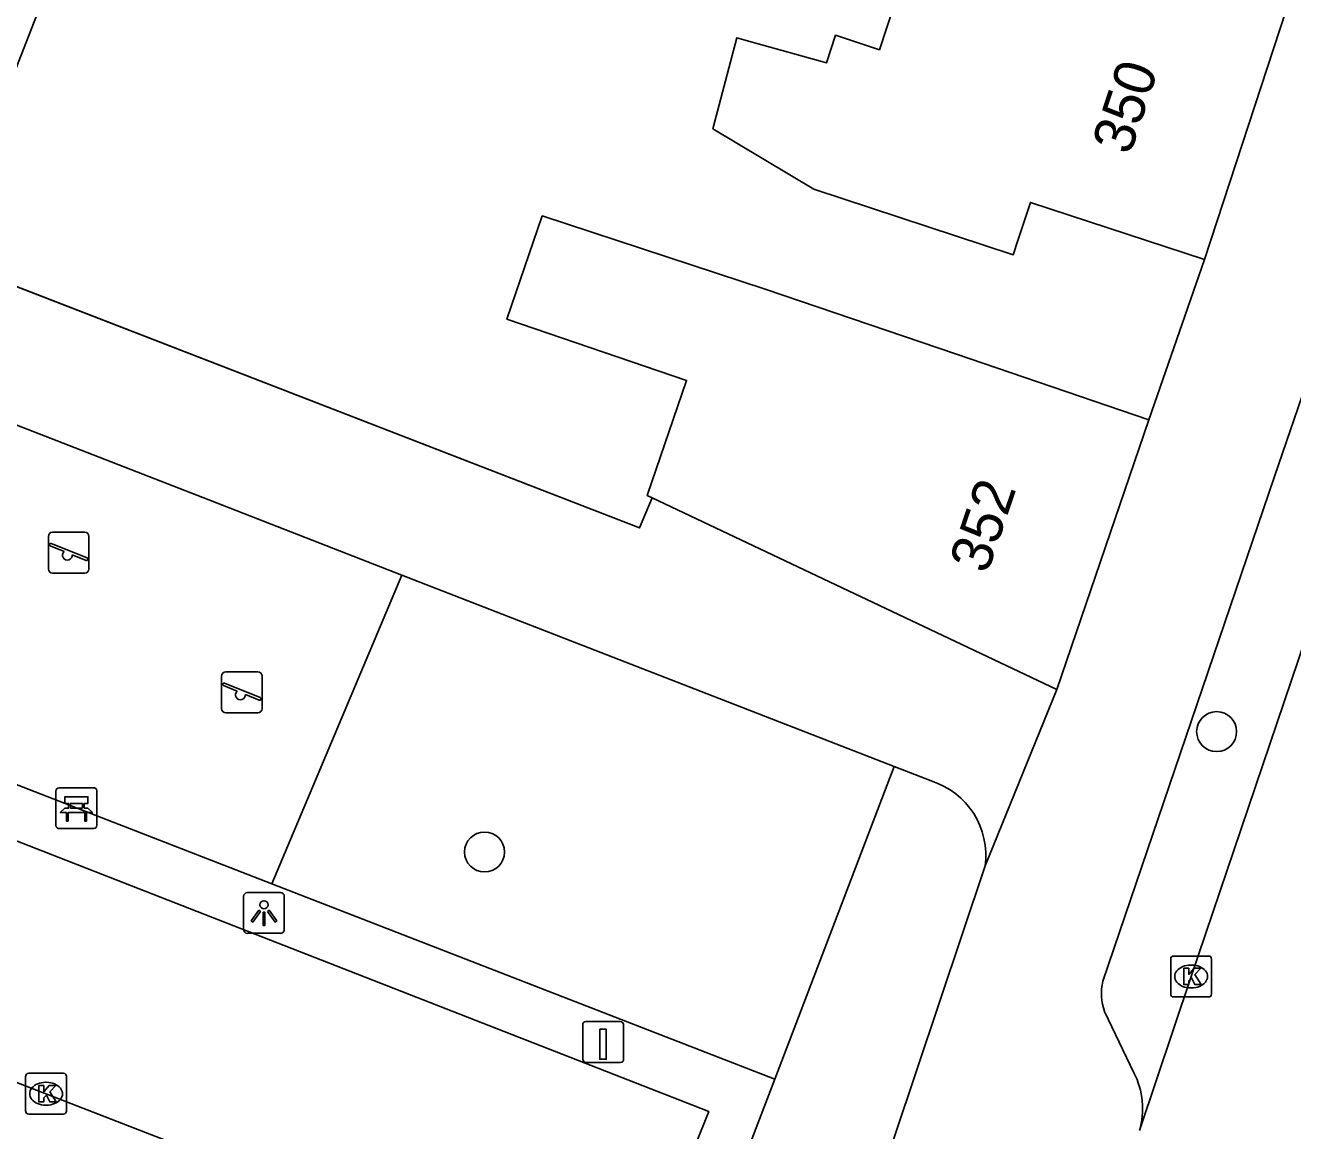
# Model space of a CAD drawing. Extents: x 161253 to 161848, y 384872 to 385383.
# Drawn here: x 161649.49 to 161680.51, y 385117.52 to 385144.57 of the extents above; entities that cross this region are included whole.
import ezdxf

# ---------------------------------------------------------------- set-up
doc = ezdxf.new("R2010")
doc.units = 0
for name, color, linetype in [('IMGEO_Bank', 7, 'Continuous'), ('IMGEO_Boom', 7, 'Continuous'), ('IMGEO_Groenvoorziening', 7, 'Continuous'), ('IMGEO_Hek', 7, 'Continuous'), ('IMGEO_Kolk', 7, 'Continuous'), ('IMGEO_Laadpaal', 7, 'Continuous'), ('IMGEO_Lichtpunt', 7, 'Continuous'), ('IMGEO_Muur', 7, 'Continuous'), ('IMGEO_Pand', 7, 'Continuous'), ('IMGEO_Pand_nummerreeks', 7, 'Continuous'), ('IMGEO_Rijbaan_lokaal_open', 7, 'Continuous'), ('IMGEO_Speelvoorziening', 7, 'Continuous'), ('IMGEO_Voetpad_open', 7, 'Continuous')]:
    doc.layers.add(name, color=color, linetype=linetype)

msp = doc.modelspace()

# ---------------------------------------------------------------- linework, layer by layer
at = {"layer": 'IMGEO_Bank'}
for p, q in [((161650.243, 385124.985), (161650.243, 385125.826)), ((161650.243, 385125.826), (161650.243, 385124.985)), ((161650.318, 385125.91), (161651.159, 385125.91)), ((161651.159, 385125.91), (161650.318, 385125.91)), ((161651.243, 385125.835), (161651.243, 385124.994)), ((161651.243, 385124.994), (161651.243, 385125.835)), ((161650.552, 385125.416), (161650.552, 385125.522)), ((161650.596, 385125.522), (161650.596, 385125.416)), ((161650.884, 385125.528), (161650.602, 385125.528)), ((161650.602, 385125.41), (161650.884, 385125.41)), ((161650.89, 385125.416), (161650.89, 385125.522)), ((161650.934, 385125.522), (161650.934, 385125.416)), ((161650.94, 385125.308), (161650.547, 385125.308)), ((161651.168, 385124.91), (161650.327, 385124.91)), ((161650.327, 385124.91), (161651.168, 385124.91))]:
    msp.add_line(p, q, dxfattribs=at)
for points in [[(161650.546, 385125.528), (161650.46, 385125.528), (161650.46, 385125.689), (161651.023, 385125.689), (161651.023, 385125.528), (161650.94, 385125.528)], [(161650.49, 385125.308), (161650.348, 385125.308), (161650.46, 385125.41), (161650.546, 385125.41)], [(161650.94, 385125.41), (161651.023, 385125.41), (161651.135, 385125.308), (161650.996, 385125.308)], [(161650.54, 385125.301), (161650.54, 385125.094), (161650.497, 385125.094), (161650.497, 385125.301)], [(161650.99, 385125.301), (161650.99, 385125.094), (161650.946, 385125.094), (161650.946, 385125.301)]]:
    msp.add_lwpolyline(points, dxfattribs=at)
for centre, radius, start, end in [((161650.321, 385125.832), 0.0779, 92.4484, 184.2845), ((161650.321, 385125.832), 0.0779, 92.4484, 184.2845), ((161651.165, 385125.832), 0.0779, 2.4484, 94.2845), ((161651.165, 385125.832), 0.0779, 2.4484, 94.2845), ((161650.545, 385125.521), 0.00671, 2.8957, 87.1043), ((161650.545, 385125.417), 0.00671, 272.8957, 357.1043), ((161650.602, 385125.521), 0.00671, 92.8957, 177.1043), ((161650.602, 385125.417), 0.00671, 182.8957, 267.1043), ((161650.884, 385125.521), 0.00671, 2.8957, 87.1043), ((161650.884, 385125.417), 0.00671, 272.8957, 357.1043), ((161650.941, 385125.521), 0.00671, 92.8957, 177.1043), ((161650.941, 385125.417), 0.00671, 182.8957, 267.1043), ((161650.49, 385125.301), 0.00671, 2.8957, 87.1043), ((161650.547, 385125.301), 0.00671, 92.8957, 177.1043), ((161650.939, 385125.301), 0.00671, 2.8957, 87.1043), ((161650.996, 385125.301), 0.00671, 92.8957, 177.1043), ((161650.321, 385124.988), 0.0779, 182.4484, 274.2845), ((161650.321, 385124.988), 0.0779, 182.4484, 274.2845), ((161651.165, 385124.988), 0.0779, 272.4484, 4.2845), ((161651.165, 385124.988), 0.0779, 272.4484, 4.2845)]:
    msp.add_arc(centre, radius, start, end, dxfattribs=at)
at = {"layer": 'IMGEO_Boom'}
for centre in [(161678.649, 385127.284), (161660.732, 385124.337)]:
    msp.add_circle(centre, 0.489, dxfattribs=at)
at = {"layer": 'IMGEO_Groenvoorziening'}
for points in [[(161658.707, 385131.117), (161655.526, 385123.562)], [(161670.754, 385126.431), (161667.834, 385118.779)]]:
    msp.add_lwpolyline(points, dxfattribs=at)
at = {"layer": 'IMGEO_Hek'}
for points in [[(161658.707, 385131.117), (161653.985, 385132.956)], [(161655.526, 385123.562), (161658.707, 385131.117)], [(161638.478, 385130.187), (161655.526, 385123.562)]]:
    msp.add_lwpolyline(points, dxfattribs=at)
at = {"layer": 'IMGEO_Kolk'}
for p, q in [((161677.524, 385120.864), (161677.524, 385121.716)), ((161677.599, 385121.79), (161678.451, 385121.79)), ((161678.525, 385121.716), (161678.525, 385120.864)), ((161678.012, 385121.57), (161678.037, 385121.57)), ((161678.035, 385121.01), (161678.01, 385121.01)), ((161678.451, 385120.79), (161677.599, 385120.79)), ((161649.501, 385117.994), (161649.501, 385118.846)), ((161649.576, 385118.92), (161650.428, 385118.92)), ((161650.502, 385118.846), (161650.502, 385117.994)), ((161649.989, 385118.7), (161650.014, 385118.7)), ((161650.428, 385117.92), (161649.576, 385117.92)), ((161650.012, 385118.14), (161649.987, 385118.14))]:
    msp.add_line(p, q, dxfattribs=at)
for points in [[(161677.524, 385120.864), (161677.524, 385121.716)], [(161677.599, 385121.79), (161678.451, 385121.79)], [(161678.525, 385121.716), (161678.525, 385120.864)], [(161677.845, 385121.49), (161677.968, 385121.49), (161677.968, 385121.339), (161678.098, 385121.49), (161678.262, 385121.49), (161678.116, 385121.339), (161678.269, 385121.09), (161678.117, 385121.09), (161678.032, 385121.254), (161677.968, 385121.187), (161677.968, 385121.09), (161677.845, 385121.09), (161677.845, 385121.49)], [(161678.451, 385120.79), (161677.599, 385120.79)], [(161649.501, 385117.994), (161649.501, 385118.846)], [(161649.576, 385118.92), (161650.428, 385118.92)], [(161650.502, 385118.846), (161650.502, 385117.994)], [(161649.822, 385118.62), (161649.945, 385118.62), (161649.945, 385118.469), (161650.075, 385118.62), (161650.239, 385118.62), (161650.093, 385118.469), (161650.246, 385118.22), (161650.094, 385118.22), (161650.009, 385118.384), (161649.945, 385118.317), (161649.945, 385118.22), (161649.822, 385118.22), (161649.822, 385118.62)], [(161650.428, 385117.92), (161649.576, 385117.92)]]:
    msp.add_lwpolyline(points, dxfattribs=at)
for centre, start, end in [((161677.601, 385121.714), 91.552, 178.448), ((161677.601, 385121.714), 91.552, 178.448), ((161678.449, 385121.714), 1.552, 88.448), ((161678.449, 385121.714), 1.552, 88.448), ((161677.601, 385120.866), 181.552, 268.448), ((161677.601, 385120.866), 181.552, 268.448), ((161678.449, 385120.866), 271.552, 358.448), ((161678.449, 385120.866), 271.552, 358.448), ((161649.578, 385118.844), 91.552, 178.448), ((161649.578, 385118.844), 91.552, 178.448), ((161650.426, 385118.844), 1.552, 88.448), ((161650.426, 385118.844), 1.552, 88.448), ((161649.578, 385117.996), 181.552, 268.448), ((161649.578, 385117.996), 181.552, 268.448), ((161650.426, 385117.996), 271.552, 358.448), ((161650.426, 385117.996), 271.552, 358.448)]:
    msp.add_arc(centre, 0.0765, start, end, dxfattribs=at)
for centre, major_axis, ratio, start_param, end_param in [((161678.011, 385121.29), (-0.387, 0.002), 0.722429, 4.712389, 7.853982), ((161678.036, 385121.29), (-0.39, 0.002), 0.717154, 1.570796, 4.712389), ((161649.988, 385118.42), (-0.387, 0.002), 0.722429, 4.712389, 7.853982), ((161650.013, 385118.42), (-0.39, 0.002), 0.717154, 1.570796, 4.712389)]:
    msp.add_ellipse(centre, major_axis=major_axis, ratio=ratio, start_param=start_param, end_param=end_param, dxfattribs=at)
at = {"layer": 'IMGEO_Laadpaal'}
for p, q in [((161663.135, 385120.102), (161663.135, 385119.261)), ((161663.135, 385120.102), (161663.135, 385119.261)), ((161664.051, 385120.186), (161663.21, 385120.186)), ((161664.051, 385120.186), (161663.21, 385120.186)), ((161664.135, 385119.27), (161664.135, 385120.111)), ((161664.135, 385119.27), (161664.135, 385120.111)), ((161663.219, 385119.186), (161664.06, 385119.186)), ((161663.219, 385119.186), (161664.06, 385119.186))]:
    msp.add_line(p, q, dxfattribs=at)
msp.add_lwpolyline([(161663.55, 385119.999), (161663.71, 385119.999), (161663.71, 385119.266), (161663.55, 385119.266), (161663.55, 385119.999)], dxfattribs=at)
for centre, start, end in [((161663.213, 385120.108), 92.4484, 184.2845), ((161663.213, 385120.108), 92.4484, 184.2845), ((161664.057, 385120.108), 2.4484, 94.2845), ((161664.057, 385120.108), 2.4484, 94.2845), ((161663.213, 385119.264), 182.4484, 274.2845), ((161663.213, 385119.264), 182.4484, 274.2845), ((161664.057, 385119.264), 272.4484, 4.2845), ((161664.057, 385119.264), 272.4484, 4.2845)]:
    msp.add_arc(centre, 0.0779, start, end, dxfattribs=at)
at = {"layer": 'IMGEO_Lichtpunt'}
for p, q in [((161654.835, 385123.248), (161654.835, 385122.441)), ((161654.835, 385123.248), (161654.835, 385122.441)), ((161655.737, 385123.343), (161654.929, 385123.343)), ((161655.737, 385123.343), (161654.929, 385123.343)), ((161655.831, 385122.441), (161655.831, 385123.248)), ((161655.831, 385122.441), (161655.831, 385123.248)), ((161654.929, 385122.347), (161655.737, 385122.347)), ((161654.929, 385122.347), (161655.737, 385122.347))]:
    msp.add_line(p, q, dxfattribs=at)
for points in [[(161655.209, 385122.912), (161655.248, 385122.884), (161655.06, 385122.622), (161655.022, 385122.649), (161655.209, 385122.912)], [(161655.311, 385122.864), (161655.358, 385122.864), (161655.358, 385122.542), (161655.311, 385122.542), (161655.311, 385122.864)], [(161655.421, 385122.884), (161655.459, 385122.911), (161655.646, 385122.649), (161655.607, 385122.621), (161655.421, 385122.884)]]:
    msp.add_lwpolyline(points, dxfattribs=at)
msp.add_circle((161655.334, 385123.046), 0.0994, dxfattribs=at)
for centre, start, end in [((161654.929, 385123.248), 90, 180), ((161654.929, 385123.248), 90, 180), ((161655.737, 385123.248), 0, 90), ((161655.737, 385123.248), 0, 90), ((161654.929, 385122.441), 180, 270), ((161654.929, 385122.441), 180, 270), ((161655.737, 385122.441), 270, 0), ((161655.737, 385122.441), 270, 360)]:
    msp.add_arc(centre, 0.0946, start, end, dxfattribs=at)
at = {"layer": 'IMGEO_Muur'}
msp.add_lwpolyline([(161664.837, 385133.005), (161664.528, 385132.269), (161646.511, 385139.25)], dxfattribs=at)
at = {"layer": 'IMGEO_Pand'}
for points in [[(161678.348, 385138.839), (161674.092, 385140.237), (161673.787, 385139.306), (161673.673, 385138.958), (161668.79, 385140.562), (161666.321, 385142.043), (161666.91, 385144.269), (161667.285, 385144.164), (161669.102, 385143.655), (161669.323, 385144.33), (161670.397, 385143.977), (161671.654, 385147.805), (161675.604, 385146.508), (161680.354, 385144.948)], [(161678.348, 385138.839), (161680.354, 385144.948)], [(161664.837, 385133.005), (161664.715, 385133.063), (161665.676, 385135.882), (161661.28, 385137.38), (161662.143, 385139.909), (161667.621, 385138.111), (161672.257, 385136.53), (161676.989, 385134.917)], [(161676.989, 385134.917), (161674.738, 385128.314)], [(161674.738, 385128.314), (161664.837, 385133.005)]]:
    msp.add_lwpolyline(points, dxfattribs=at)
at = {"layer": 'IMGEO_Rijbaan_lokaal_open'}
for points in [[(161709.972, 385215.524), (161709.434, 385213.92), (161706.035, 385204.164), (161703.571, 385196.929), (161697.189, 385177.941), (161690.517, 385158.313), (161684.5, 385140.421), (161678.025, 385121.29), (161676.761, 385117.516)], [(161665.69, 385112.325), (161625.181, 385128.058), (161624.4, 385128.348)]]:
    msp.add_lwpolyline(points, dxfattribs=at)
at = {"layer": 'IMGEO_Speelvoorziening'}
for p, q in [((161650.158, 385132.164), (161650.948, 385132.164)), ((161650.948, 385132.164), (161650.158, 385132.164)), ((161650.058, 385131.264), (161650.058, 385132.064)), ((161650.058, 385132.064), (161650.058, 385131.264)), ((161650.127, 385131.889), (161651.003, 385131.536)), ((161651.048, 385132.064), (161651.048, 385131.264)), ((161651.048, 385131.264), (161651.048, 385132.064)), ((161650.441, 385131.692), (161650.102, 385131.829)), ((161650.979, 385131.476), (161650.639, 385131.613)), ((161650.948, 385131.164), (161650.158, 385131.164)), ((161650.158, 385131.164), (161650.948, 385131.164)), ((161654.297, 385127.845), (161654.297, 385128.645)), ((161654.297, 385128.645), (161654.297, 385127.845)), ((161654.366, 385128.47), (161655.242, 385128.117)), ((161654.397, 385128.745), (161655.187, 385128.745)), ((161655.187, 385128.745), (161654.397, 385128.745)), ((161655.287, 385128.645), (161655.287, 385127.845)), ((161655.287, 385127.845), (161655.287, 385128.645)), ((161654.68, 385128.273), (161654.341, 385128.41)), ((161655.218, 385128.057), (161654.878, 385128.194)), ((161655.187, 385127.745), (161654.397, 385127.745)), ((161654.397, 385127.745), (161655.187, 385127.745))]:
    msp.add_line(p, q, dxfattribs=at)
for centre, radius, start, end in [((161650.158, 385132.064), 0.1, 90, 180), ((161650.158, 385132.064), 0.1, 90, 180), ((161650.948, 385132.064), 0.1, 0, 90), ((161650.948, 385132.064), 0.1, 360, 90), ((161650.115, 385131.859), 0.0327, 68.078, 248.078), ((161650.52, 385131.602), 0.12, 130.9928, 5.1632), ((161650.158, 385131.264), 0.1, 180, 270), ((161650.158, 385131.264), 0.1, 180, 270), ((161650.948, 385131.264), 0.1, 270, 0), ((161650.948, 385131.264), 0.1, 270, 0), ((161650.991, 385131.506), 0.0327, 248.078, 68.078), ((161654.397, 385128.645), 0.1, 90, 180), ((161654.397, 385128.645), 0.1, 90, 180), ((161654.354, 385128.44), 0.0327, 68.078, 248.078), ((161655.187, 385128.645), 0.1, 0, 90), ((161655.187, 385128.645), 0.1, 360, 90), ((161654.759, 385128.183), 0.12, 130.9928, 5.1632), ((161654.397, 385127.845), 0.1, 180, 270), ((161654.397, 385127.845), 0.1, 180, 270), ((161655.187, 385127.845), 0.1, 270, 0), ((161655.187, 385127.845), 0.1, 270, 0), ((161655.23, 385128.087), 0.0327, 248.078, 68.078)]:
    msp.add_arc(centre, radius, start, end, dxfattribs=at)
at = {"layer": 'IMGEO_Voetpad_open'}
for points in [[(161675.862, 385121.175), (161680.062, 385133.527), (161681.519, 385137.762), (161697.7, 385185.702), (161699.123, 385189.971), (161699.788, 385191.873), (161700.995, 385195.418), (161704.317, 385205.403), (161706.349, 385211.281), (161718.722, 385245.02), (161720.533, 385250), (161723.07, 385256.974), (161724.343, 385260.467), (161728.45, 385271.788), (161730.055, 385276.02), (161737.81, 385297.45), (161738.417, 385297.998), (161739.782, 385298.62)], [(161654.38, 385156.66), (161647.453, 385138.885)], [(161647.453, 385138.885), (161664.528, 385132.269), (161664.837, 385133.005)], [(161676.989, 385134.917), (161678.348, 385138.839)], [(161641.434, 385137.837), (161649.392, 385134.744), (161653.985, 385132.956), (161658.707, 385131.117)], [(161628.462, 385132.746), (161666.218, 385117.983), (161664.935, 385114.778), (161664.87, 385114.619), (161664.819, 385114.456), (161664.784, 385114.288), (161664.763, 385114.118), (161664.757, 385113.947), (161664.767, 385113.775), (161664.792, 385113.606), (161664.832, 385113.439), (161664.887, 385113.277), (161664.956, 385113.12), (161665.039, 385112.97), (161665.135, 385112.828), (161665.243, 385112.695), (161665.363, 385112.572), (161665.493, 385112.46), (161665.632, 385112.361), (161665.69, 385112.325)], [(161658.707, 385131.117), (161670.754, 385126.431)], [(161655.526, 385123.562), (161638.478, 385130.187)], [(161672.982, 385123.995), (161674.738, 385128.314)], [(161670.754, 385126.431), (161671.666, 385126.076)], [(161669.637, 385114.013), (161672.982, 385123.995)], [(161667.834, 385118.779), (161655.526, 385123.562)], [(161676.625, 385118.931), (161675.904, 385120.43)], [(161668.21, 385113.199), (161666.971, 385113.655), (161666.927, 385113.692), (161666.83, 385113.783), (161666.742, 385113.882), (161666.662, 385113.989), (161666.593, 385114.103), (161666.534, 385114.222), (161666.487, 385114.346), (161666.45, 385114.474), (161666.425, 385114.605), (161666.412, 385114.737), (161666.41, 385114.87), (161666.421, 385115.003), (161666.443, 385115.134), (161667.834, 385118.779)]]:
    msp.add_lwpolyline(points, dxfattribs=at)
for centre, radius, start, end in [((161671.092, 385124.256), 1.908, 352.1252, 72.4924), ((161677.192, 385120.876), 1.363, 167.34, 199.1133), ((161674.907, 385118.052), 1.93, 343.8764, 27.1036)]:
    msp.add_arc(centre, radius, start, end, dxfattribs=at)

# ---------------------------------------------------------------- texts
at = {"layer": 'IMGEO_Pand_nummerreeks'}
for s, rotation, p in [('350', 71.8203, (161676.528, 385141.372)), ('352', 71.1755, (161673.033, 385131.121))]:
    msp.add_text(s, height=1, rotation=rotation, dxfattribs=at).set_placement(p)

doc.saveas('drawing.dxf')
